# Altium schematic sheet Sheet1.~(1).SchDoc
size A4; SheetNumber: 1; SheetTotal: 1
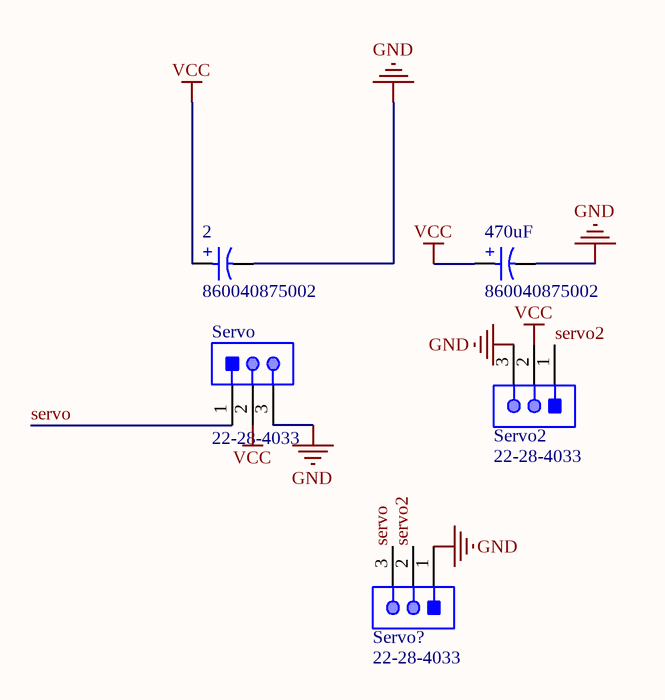
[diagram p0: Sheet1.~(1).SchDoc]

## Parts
2  860040875002  [WCAP-ATUL_D10H12.5]
470uF  860040875002  [WCAP-ATUL_D10H12.5]
Servo  22-28-4033  [MOLX-22-28-4033_V]
Servo2  22-28-4033  [MOLX-22-28-4033_V]
Servo?  22-28-4033  [MOLX-22-28-4033_V]

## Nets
GND: 2.2(N) 470uF.2(N) Servo.3 Servo2.3 Servo?.1
VCC: 2.1(P) 470uF.1(P) Servo.2 Servo2.2
servo: Servo.1 Servo?.3
servo2: Servo2.1 Servo?.2

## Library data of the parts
2 470uF = CMP-03913-53914322-1: 860040875002 WCAP-ATUL Aluminum Electrolytic Capacitors; Pitch: 5mm; Voltage Rating: 100V; Tolerance: 20%; Polarity: Polar; Ripple Current: 400mA; Capacitance: 47µF; Life (Hours): 7000hours; Leakage Current: 47µA; Impedance: 420mΩ
Servo Servo2 Servo? = CMP-1676-00001-5: Male Header, Pitch 2.54 mm, 1 x 3 Position, Height 8.38 mm, Tail Length 3.18 mm, RoHS, Bulk; Manufacturer: Molex; Rows: 1; Voltage Rating: 250 V; Current Rating: 4 A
